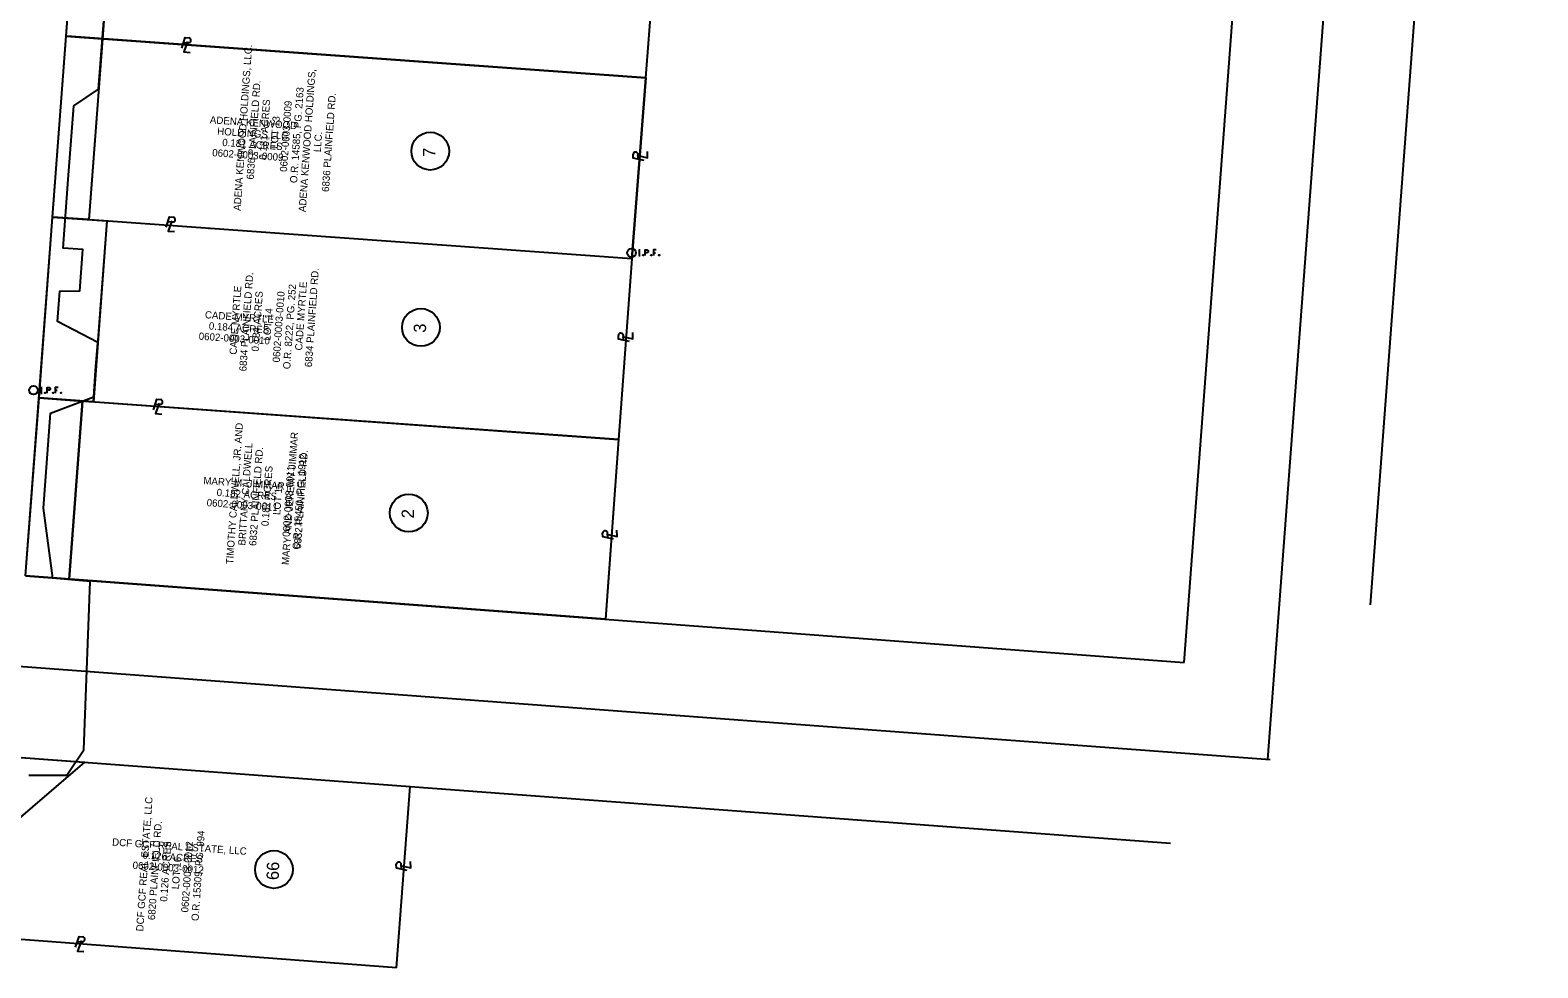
# Model space of a CAD drawing. Extents: x 204354 to 231038, y 361459 to 365260.
# Drawn here: x 220550.5 to 220965.9, y 361477.8 to 361736.1 of the extents above; entities that cross this region are included whole.
import ezdxf

# ---------------------------------------------------------------- set-up
doc = ezdxf.new("R2010")
doc.units = 0
for name, color, linetype in [('CM_Corridor_Conceptual', 7, 'Continuous'), ('CM_Corridor_Point_Control', 7, 'Continuous'), ('CM_Corridor_Range_Conceptual', 7, 'Continuous'), ('DT_P_Contour_Minor', 7, 'Continuous'), ('DT_P_Contour_Text', 7, 'Continuous'), ('DT_P_Triangles', 7, 'Continuous'), ('DT_X_Contour_Minor', 7, 'Continuous'), ('MD_P_Intersection_MatchLine', 7, 'Continuous'), ('MD_P_Surface_Finished_Grade', 7, 'Continuous'), ('MD_P_SW_BOT', 7, 'Continuous'), ('PV_P_Walk', 7, 'Continuous'), ('SC_Shading1', 7, 'Continuous')]:
    doc.layers.add(name, color=color, linetype=linetype)

msp = doc.modelspace()

# ---------------------------------------------------------------- linework, layer by layer
at = {"layer": 'CM_Corridor_Conceptual'}
for centre in [(220602.98, 361731.44), (220599.74, 361681.54), (220596.55, 361631.64), (220631, 361579.65)]:
    msp.add_circle(centre, 0.05, dxfattribs=at)
at = {"layer": 'CM_Corridor_Range_Conceptual'}
for p, q in [((220891.46, 361535.2), (220942.8, 362219.1)), ((220153.72, 361590.23), (220892.08, 361535.15))]:
    msp.add_line(p, q, dxfattribs=at)
at = {"layer": 'DT_P_Contour_Text'}
for centre in [(220660.71, 361702.8), (220658.14, 361654.23), (220654.8, 361603.09), (220617.63, 361504.86)]:
    msp.add_circle(centre, 5.2, dxfattribs=at)
at = {"layer": 'DT_P_Triangles'}
msp.add_lwpolyline([(220550.14, 361530.84), (220560.58, 361530.82), (220565.23, 361537.79), (220567.05, 361584.23), (220556.71, 361585.16), (220554.16, 361604.45), (220556.12, 361630.61), (220567.99, 361635.08), (220568.53, 361642.29), (220569.11, 361650.04), (220558.02, 361655.86), (220558.64, 361664.19), (220564.17, 361664.34), (220565.02, 361675.69), (220559.54, 361676.1), (220560.96, 361695.01), (220562.48, 361715.28), (220569.34, 361719.9), (220571.38, 361747.03)], dxfattribs=at)
at = {"layer": 'MD_P_Intersection_MatchLine'}
for p, q in [((220574.13, 361783.64), (220570.38, 361733.77)), ((220560.34, 361734.5), (220570.38, 361733.78)), ((220560.41, 361734.5), (220570.38, 361733.78)), ((220570.38, 361733.77), (220566.64, 361683.9)), ((220570.38, 361733.77), (220566.64, 361683.92)), ((220556.67, 361684.64), (220571.63, 361683.56)), ((220571.63, 361683.55), (220567.88, 361633.69)), ((220552.92, 361634.78), (220567.89, 361633.7)), ((220552.92, 361634.78), (220567.89, 361633.7)), ((220561.21, 361584.86), (220564.89, 361633.91)), ((220565.45, 361534.41), (220544, 361515.95))]:
    msp.add_line(p, q, dxfattribs=at)
at = {"layer": 'MD_P_Surface_Finished_Grade'}
for points in [[(220718.2, 361675.6), (220718.56, 361675.6)], [(220718.38, 361674), (220718.38, 361675.6)], [(220719.95, 361674), (220719.95, 361675.6), (220720.47, 361675.6), (220720.53, 361675.58), (220720.61, 361675.56), (220720.64, 361675.53), (220720.67, 361675.51), (220720.72, 361675.44), (220720.75, 361675.38), (220720.77, 361675.28), (220720.77, 361675.13), (220720.76, 361675.08), (220720.74, 361675), (220720.69, 361674.92), (220720.65, 361674.88), (220720.62, 361674.85), (220720.56, 361674.83), (220720.47, 361674.81), (220719.95, 361674.81)], [(220722.95, 361675.6), (220722.19, 361675.6), (220722.19, 361674)], [(220722.19, 361674.81), (220722.73, 361674.81)], [(220718.2, 361674), (220718.56, 361674)], [(220719.34, 361674.21), (220719.39, 361674.21), (220719.43, 361674.19), (220719.46, 361674.13), (220719.46, 361674.07), (220719.43, 361674.02), (220719.39, 361674), (220719.34, 361674), (220719.31, 361674.02), (220719.27, 361674.07), (220719.27, 361674.13), (220719.31, 361674.19), (220719.34, 361674.21)], [(220721.59, 361674.21), (220721.64, 361674.21), (220721.68, 361674.19), (220721.71, 361674.13), (220721.71, 361674.07), (220721.68, 361674.02), (220721.64, 361674), (220721.59, 361674), (220721.55, 361674.02), (220721.52, 361674.07), (220721.52, 361674.13), (220721.55, 361674.19), (220721.59, 361674.21)], [(220723.74, 361674.21), (220723.79, 361674.21), (220723.83, 361674.19), (220723.86, 361674.13), (220723.86, 361674.07), (220723.83, 361674.02), (220723.79, 361674), (220723.74, 361674), (220723.7, 361674.02), (220723.67, 361674.07), (220723.67, 361674.13), (220723.7, 361674.19), (220723.74, 361674.21)], [(220553.41, 361637.7), (220553.76, 361637.7)], [(220553.59, 361636.1), (220553.59, 361637.7)], [(220555.15, 361636.1), (220555.15, 361637.7), (220555.68, 361637.7), (220555.74, 361637.69), (220555.81, 361637.66), (220555.85, 361637.64), (220555.88, 361637.61), (220555.92, 361637.55), (220555.96, 361637.49), (220555.98, 361637.39), (220555.98, 361637.24), (220555.97, 361637.19), (220555.95, 361637.11), (220555.9, 361637.02), (220555.86, 361636.98), (220555.83, 361636.96), (220555.77, 361636.93), (220555.68, 361636.92), (220555.15, 361636.92)], [(220558.16, 361637.7), (220557.4, 361637.7), (220557.4, 361636.1)], [(220553.41, 361636.1), (220553.76, 361636.1)], [(220554.55, 361636.32), (220554.6, 361636.32), (220554.64, 361636.29), (220554.67, 361636.24), (220554.67, 361636.18), (220554.64, 361636.13), (220554.6, 361636.1), (220554.55, 361636.1), (220554.51, 361636.13), (220554.48, 361636.18), (220554.48, 361636.24), (220554.51, 361636.29), (220554.55, 361636.32)], [(220556.8, 361636.32), (220556.85, 361636.32), (220556.88, 361636.29), (220556.92, 361636.24), (220556.92, 361636.18), (220556.88, 361636.13), (220556.85, 361636.1), (220556.8, 361636.1), (220556.76, 361636.13), (220556.73, 361636.18), (220556.73, 361636.24), (220556.76, 361636.29), (220556.8, 361636.32)], [(220557.4, 361636.92), (220557.94, 361636.92)], [(220558.94, 361636.32), (220559, 361636.32), (220559.03, 361636.29), (220559.07, 361636.24), (220559.07, 361636.18), (220559.03, 361636.13), (220559, 361636.1), (220558.94, 361636.1), (220558.91, 361636.13), (220558.88, 361636.18), (220558.88, 361636.24), (220558.91, 361636.29), (220558.94, 361636.32)]]:
    msp.add_lwpolyline(points, dxfattribs=at)
for centre in [(220716.19, 361674.8), (220551.4, 361636.9)]:
    msp.add_circle(centre, 1.2, dxfattribs=at)
at = {"layer": 'MD_P_SW_BOT'}
for p, q in [((220720.14, 361723.02), (220723.92, 361772.87)), ((220720.14, 361723.02), (220560.55, 361734.48)), ((220592.77, 361732.77), (220594.07, 361732.68)), ((220593.53, 361732.09), (220593.53, 361732.09)), ((220716.21, 361673.17), (220720.14, 361723.02)), ((220718, 361700.6), (220717.96, 361701.9)), ((220718.6, 361701.42), (220718.6, 361701.42)), ((220716.21, 361673.17), (220556.68, 361684.63)), ((220588.45, 361683.39), (220589.74, 361683.29)), ((220589.2, 361682.71), (220589.2, 361682.71)), ((220716.21, 361673.17), (220712.6, 361623.3)), ((220713.95, 361650.69), (220713.91, 361651.98)), ((220714.55, 361651.51), (220714.55, 361651.51)), ((220712.6, 361623.3), (220552.97, 361634.77)), ((220584.96, 361633.11), (220586.25, 361633.01)), ((220585.71, 361632.43), (220585.71, 361632.43)), ((220712.6, 361623.3), (220709.02, 361573.95)), ((220709.61, 361596.22), (220709.57, 361597.51)), ((220710.21, 361597.04), (220710.21, 361597.04)), ((220651.45, 361477.75), (220655.2, 361527.71)), ((220652.76, 361504.93), (220652.72, 361506.23)), ((220653.36, 361505.76), (220653.36, 361505.76)), ((220651.45, 361477.75), (220541.76, 361486.03)), ((220563.49, 361485.01), (220564.79, 361484.91)), ((220564.25, 361484.32), (220564.25, 361484.32))]:
    msp.add_line(p, q, dxfattribs=at)
for points in [[(220592.24, 361731.21), (220593.23, 361734.11), (220594.26, 361734.04)], [(220593.86, 361733.03), (220592.86, 361730.14), (220594.6, 361730.01)], [(220719.61, 361700.24), (220716.62, 361700.91), (220716.58, 361701.94)], [(220717.63, 361701.66), (220720.61, 361700.97), (220720.55, 361702.72)], [(220587.92, 361681.83), (220588.91, 361684.73), (220589.94, 361684.65)], [(220589.54, 361683.64), (220588.54, 361680.75), (220590.28, 361680.63)], [(220715.56, 361650.32), (220712.57, 361651), (220712.53, 361652.03)], [(220713.58, 361651.74), (220716.56, 361651.06), (220716.5, 361652.8)], [(220584.43, 361631.55), (220585.42, 361634.45), (220586.45, 361634.38)], [(220586.05, 361633.37), (220585.05, 361630.48), (220586.79, 361630.35)], [(220711.22, 361595.85), (220708.23, 361596.53), (220708.19, 361597.56)], [(220709.24, 361597.27), (220712.22, 361596.59), (220712.16, 361598.33)], [(220654.37, 361504.57), (220651.38, 361505.24), (220651.34, 361506.28)], [(220652.39, 361505.99), (220655.37, 361505.3), (220655.31, 361507.05)], [(220562.96, 361483.45), (220563.96, 361486.35), (220564.99, 361486.27)], [(220564.59, 361485.26), (220563.57, 361482.37), (220565.31, 361482.24)]]:
    msp.add_lwpolyline(points, dxfattribs=at)
for centre, start, end in [((220594.11, 361733.37), 266.3604, 77.2175), ((220717.27, 361701.87), 2.5465, 173.4036), ((220589.79, 361683.98), 266.3266, 77.1838), ((220713.22, 361651.95), 2.5465, 173.4036), ((220586.3, 361633.7), 266.3266, 77.1838), ((220708.88, 361597.48), 2.5465, 173.4036), ((220652.03, 361506.2), 2.5465, 173.4036), ((220564.83, 361485.6), 266.1539, 77.011)]:
    msp.add_arc(centre, 0.69, start, end, dxfattribs=at)
at = {"layer": 'PV_P_Walk'}
for p, q in [((220919.73, 361577.82), (220965.86, 362192.34)), ((220868.4, 361561.94), (220915.12, 362184.41)), ((220549.24, 361585.75), (220590.37, 362133.66)), ((220549.24, 361585.75), (220590.37, 362133.66)), ((220549.24, 361585.75), (220868.4, 361561.94)), ((220545.5, 361535.89), (220864.68, 361512.08))]:
    msp.add_line(p, q, dxfattribs=at)
at = {"layer": 'SC_Shading1'}
for points in [[(220560.41, 361734.5), (220564.15, 361784.36), (220574.13, 361783.64), (220570.38, 361733.78)], [(220556.67, 361684.64), (220560.41, 361734.5), (220570.38, 361733.78), (220566.64, 361683.92)], [(220716.21, 361673.17), (220556.67, 361684.64), (220560.41, 361734.5), (220720.14, 361723.02)], [(220552.92, 361634.78), (220556.67, 361684.64), (220571.63, 361683.56), (220567.89, 361633.7)], [(220549.24, 361585.75), (220552.92, 361634.78), (220564.89, 361633.91), (220561.21, 361584.86)], [(220549.24, 361585.75), (220552.92, 361634.78), (220712.6, 361623.3), (220709.01, 361573.83)], [(220545.5, 361535.89), (220565.45, 361534.41), (220544, 361515.95)]]:
    msp.add_lwpolyline(points, close=True, dxfattribs=at)

# ---------------------------------------------------------------- texts
at = {"layer": 'CM_Corridor_Point_Control'}
for s, p in [('ADENA KENWOOD HOLDINGS,', (220626.39, 361685.97)), ('6836 PLAINFIELD RD.', (220632.79, 361691.51)), ('LLC.', (220630.55, 361702.47)), ('6834 PLAINFIELD RD.', (220628.1, 361643.22)), ('CADE MYRTLE', (220625.42, 361647.81)), ('MARY AND JEREMY JIMMAR', (220621.76, 361588.71)), ('6832 PLAINFIELD RD.', (220625.08, 361593.13))]:
    msp.add_text(s, height=2, rotation=86, dxfattribs=at).set_placement(p)
at = {"layer": 'DT_P_Contour_Minor'}
for s, p in [('ADENA KENWOOD HOLDINGS, LLC.', (220608.45, 361686.31)), ('6836 PLAINFIELD RD.', (220612.06, 361694.93)), ('O.R. 14585, PG. 2163', (220624.02, 361693.95)), (' 0.181 ACRES', (220615.4, 361699.65)), ('0602-0003-0009', (220621.23, 361697.04)), ('LOT 13', (220618.67, 361703.47)), ('6834 PLAINFIELD RD.', (220610.05, 361642.07)), ('CADE MYRTLE', (220607.36, 361646.65)), (' 0.184 ACRES', (220613.39, 361646.79)), (' 0602-0003-0010', (220619.19, 361643.79)), ('O.R. 8222, PG. 252', (220622.12, 361642.67)), ('LOT 14', (220616.66, 361650.55)), ('TIMOTHY CALDWELL, JR. AND ', (220606.39, 361588.89)), ('BRITTANY CALDWELL', (220609.76, 361594.08)), ('6832 PLAINFIELD RD.', (220612.76, 361593.96)), ('O.R. 15450, PG. 1912', (220624.72, 361592.97)), (' 0.182 ACRES', (220616.09, 361598.67)), (' 0602-0003-0011', (220621.9, 361595.71)), ('LOT 15', (220619.37, 361602.49)), ('DCF GCF REAL ESTATE, LLC', (220581.63, 361487.74)), ('6820 PLAINFIELD RD.', (220584.86, 361490.86)), ('0.126 ACRES', (220588.22, 361495.93)), ('0602-0003-0012', (220594.03, 361492.97)), ('O.R. 15309, PG. 994', (220596.87, 361490.61)), ('LOT 16', (220591.47, 361499.36))]:
    msp.add_text(s, height=2, rotation=86, dxfattribs=at).set_placement(p)
at = {"layer": 'DT_P_Contour_Text'}
for s, p in [('7', (220662.08, 361701.13)), ('3', (220659.52, 361652.73)), ('2', (220656.18, 361601.58)), ('66', (220618.97, 361501.9))]:
    msp.add_text(s, height=3.4, rotation=88.3143, dxfattribs=at).set_placement(p)
at = {"layer": 'DT_X_Contour_Minor'}
for s, p in [('ADENA KENWOOD ', (220599.94, 361710.49)), ('HOLDINGS,LLC.', (220601.96, 361707.34)), ('0.181 ACRES', (220603.35, 361704.24)), ('0602-0003-0009', (220600.6, 361701.42)), ('CADE MYRTLE', (220598.58, 361656.76)), (' 0.184 ACRES', (220598.92, 361653.73)), (' 0602-0003-0010', (220596.13, 361650.92)), ('MARY M. JIMMAR', (220598.15, 361611.06)), (' 0.182 ACRES', (220601.07, 361607.85)), (' 0602-0003-0011', (220598.32, 361605.04)), ('DCF GCF REAL ESTATE, LLC', (220573.01, 361511.48)), ('0.126 ACRES', (220581.41, 361507.88)), ('0602-0003-0012', (220578.66, 361505.07))]:
    msp.add_text(s, height=2, rotation=356, dxfattribs=at).set_placement(p)

doc.saveas('drawing.dxf')
